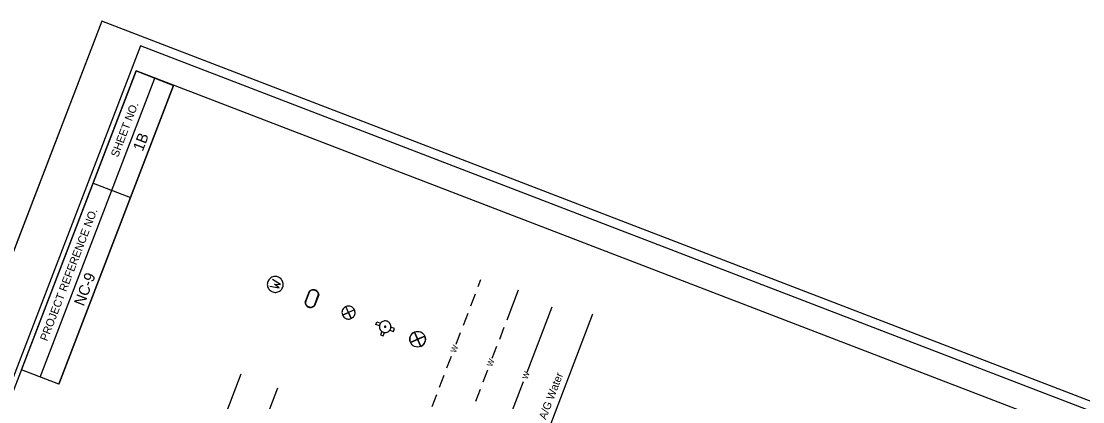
# Model space of a CAD drawing. Extents: x 1015221 to 1064345, y 619216 to 647967.
# Drawn here: x 1047324 to 1051569, y 635845 to 637366 of the extents above; entities that cross this region are included whole.
import ezdxf

# ---------------------------------------------------------------- set-up
doc = ezdxf.new("R2010")
doc.units = 0
for name, color, linetype in [('Default', 7, 'Continuous'), ('Sheet Cutting Line CELL', 7, 'Continuous'), ('Sheet Data Field CELL', 7, 'Continuous'), ('Sheet Plot Border Inside CELL', 7, 'Continuous'), ('Sheet Plot Border Outside CELL', 7, 'Continuous'), ('Sheet Symbology CELL', 7, 'Continuous')]:
    doc.layers.add(name, color=color, linetype=linetype)

msp = doc.modelspace()

# ---------------------------------------------------------------- linework, layer by layer
at = {"layer": 'Default'}
for p, q in [((1049151.2, 636304.8), (1049162.2, 636333.7)), ((1048458.7, 636242.1), (1048476, 636287.1)), ((1048460.2, 636241.5), (1048477.4, 636286.5)), ((1048511.7, 636273), (1048494.6, 636228.3)), ((1048513.2, 636272.5), (1048496, 636227.8)), ((1049121.6, 636227.9), (1049139.9, 636275.5)), ((1049266.5, 636172.3), (1049312.4, 636291.7)), ((1049346.7, 635962.7), (1049447.2, 636224.2)), ((1049092.1, 636151), (1049110.4, 636198.6)), ((1049373.4, 635580.1), (1049609.8, 636195.4)), ((1049237, 636095.3), (1049255.3, 636143)), ((1049062.5, 636074.1), (1049080.8, 636121.7)), ((1049207.4, 636018.4), (1049225.7, 636066.1)), ((1049026.2, 635979.6), (1049044.5, 636027.2)), ((1048201.7, 635954.5), (1047744.7, 634765.2)), ((1049171.1, 635924), (1049189.4, 635971.6)), ((1048996.7, 635902.7), (1049015, 635950.3)), ((1049222.1, 635638.2), (1049332.7, 635926.1)), ((1048348.2, 635898.3), (1047847.2, 634594.3)), ((1048967.1, 635825.8), (1048985.4, 635873.4)), ((1049141.6, 635847.1), (1049159.9, 635894.7))]:
    msp.add_line(p, q, dxfattribs=at)
for points in [[(1048309.9, 636324.9), (1048308.7, 636321), (1048308, 636317.2), (1048307.8, 636313.2), (1048308.2, 636309.2), (1048308.9, 636305.4), (1048310.2, 636301.6), (1048312, 636297.9), (1048314.1, 636294.7), (1048316.7, 636291.5), (1048319.8, 636288.9), (1048323, 636286.6), (1048326.4, 636284.7), (1048330.2, 636283.3), (1048333.9, 636282.4), (1048338.1, 636281.9), (1048341.9, 636281.8), (1048346, 636282.4), (1048349.6, 636283.4), (1048353.5, 636285), (1048357, 636286.9), (1048360.1, 636289.3), (1048363, 636292), (1048365.6, 636295.1), (1048367.7, 636298.6), (1048369.3, 636302.1), (1048370.6, 636306), (1048371.2, 636309.8), (1048371.4, 636313.9), (1048371, 636317.8), (1048370.3, 636321.6), (1048369, 636325.4), (1048367.2, 636329.1), (1048365.1, 636332.4), (1048362.6, 636335.5), (1048359.4, 636338.1), (1048356.2, 636340.4), (1048352.8, 636342.3), (1048349, 636343.7), (1048345.3, 636344.6), (1048341.1, 636345.1), (1048337.3, 636345.2), (1048333.3, 636344.6), (1048329.6, 636343.6), (1048325.7, 636342), (1048322.3, 636340.1), (1048319.2, 636337.7), (1048316.2, 636335.1), (1048313.7, 636331.9), (1048311.5, 636328.4), (1048309.9, 636324.9)], [(1048318.1, 636306.5), (1048355.2, 636299.3), (1048336, 636314.9), (1048360.8, 636313.8), (1048328.4, 636333.4)], [(1048475.9, 636286.8), (1048478.5, 636289.2), (1048481.5, 636291), (1048485.1, 636292.4), (1048488.4, 636293.1), (1048492.2, 636293.4), (1048495.8, 636293), (1048499.1, 636292.1), (1048502.6, 636290.4), (1048505.4, 636288.3), (1048507.8, 636285.7), (1048510.1, 636282.8), (1048511.5, 636279.5), (1048512.6, 636276.1), (1048513.2, 636272.5)], [(1048476.8, 636285.8), (1048479.5, 636288.4), (1048482.9, 636290.2), (1048486, 636291.3), (1048489.6, 636292), (1048493.3, 636291.9), (1048497.1, 636291.1), (1048500.3, 636289.9), (1048503.6, 636288), (1048506.1, 636285.7), (1048508.4, 636282.7), (1048510.1, 636279.4), (1048511.2, 636275.9), (1048511.8, 636272.3)], [(1048458.7, 636242.1), (1048459, 636238.6), (1048460.1, 636235.2), (1048461.8, 636231.8), (1048463.8, 636229), (1048466.4, 636226.3), (1048469.3, 636224.2), (1048472.5, 636222.6), (1048476.1, 636221.6), (1048479.7, 636221.2), (1048483.2, 636221.6), (1048486.8, 636222.2), (1048490.1, 636223.6), (1048493.1, 636225.5), (1048496, 636227.8)], [(1048460.1, 636242.3), (1048460.7, 636238.6), (1048461.8, 636235.2), (1048463.5, 636231.8), (1048465.5, 636229), (1048468.3, 636226.6), (1048471.6, 636224.7), (1048474.8, 636223.4), (1048478.3, 636222.8), (1048481.9, 636222.7), (1048485.6, 636223.3), (1048489.1, 636224.7), (1048492.2, 636226.5), (1048494.8, 636228.9)], [(1048641.9, 636225.3), (1048638.3, 636226.4), (1048634.2, 636227), (1048630.5, 636226.9), (1048626.5, 636226.2), (1048622.9, 636225.1), (1048619.5, 636223.4), (1048616.2, 636221.2), (1048613.3, 636218.6), (1048610.9, 636215.5), (1048609, 636212.2), (1048607.5, 636208.4), (1048606.7, 636204.7), (1048606.4, 636200.8), (1048606.8, 636196.9), (1048607.8, 636193.1), (1048609.2, 636189.5), (1048611.1, 636186.2), (1048613.6, 636183.1), (1048616.3, 636180.5), (1048619.8, 636178.2), (1048623.2, 636176.6), (1048626.8, 636175.5), (1048630.9, 636174.9), (1048634.7, 636175), (1048638.7, 636175.7), (1048642.2, 636176.8), (1048645.7, 636178.5), (1048649, 636180.7), (1048651.9, 636183.3), (1048654.3, 636186.4), (1048656.2, 636189.7), (1048657.6, 636193.5), (1048658.5, 636197.2), (1048658.7, 636201.1), (1048658.3, 636205), (1048657.3, 636208.8), (1048655.9, 636212.4), (1048654, 636215.7), (1048651.5, 636218.8), (1048648.8, 636221.4), (1048645.3, 636223.7), (1048641.9, 636225.3)], [(1048656.5, 636211.6), (1048608.6, 636190.3), (1048632.6, 636201), (1048643.2, 636177), (1048621.9, 636224.9)], [(1048757.3, 636152.7), (1048756.3, 636149.2), (1048755.8, 636145.5), (1048755.9, 636141.6), (1048756.8, 636138), (1048758.1, 636134.7), (1048760.1, 636131.3), (1048762.5, 636128.4), (1048765.4, 636126), (1048768.5, 636123.9), (1048771.9, 636122.6), (1048775.5, 636121.9), (1048779.2, 636121.4), (1048782.9, 636121.9), (1048786.5, 636122.8), (1048790, 636124.3), (1048793.3, 636126.3), (1048795.9, 636128.8), (1048798.3, 636131.8), (1048800.2, 636135), (1048801.5, 636138.3), (1048802.2, 636141.9), (1048802.1, 636145.8), (1048801.9, 636149.5), (1048800.7, 636153.1), (1048799, 636156.4), (1048797, 636159.4), (1048794.2, 636162.1), (1048791.2, 636164.5), (1048787.9, 636166.1), (1048784.5, 636167.1), (1048780.9, 636167.8), (1048777, 636167.7), (1048773.2, 636167.2), (1048769.8, 636166), (1048766.5, 636164), (1048763.4, 636162), (1048761, 636159), (1048758.9, 636156), (1048757.3, 636152.7)], [(1048755.9, 636147.4), (1048741.9, 636152.8), (1048746.2, 636164.1), (1048760.5, 636158.6)], [(1048765.4, 636126), (1048760, 636112), (1048771.3, 636107.7), (1048776.7, 636121.7)], [(1048776.5, 636145.6), (1048776.4, 636144.4), (1048776.9, 636143.2), (1048777.8, 636142.2), (1048779, 636142.1), (1048780.4, 636142.2), (1048781.4, 636143.1), (1048781.8, 636144.3), (1048781.7, 636145.6), (1048780.8, 636146.6), (1048779.8, 636147.3), (1048778.4, 636147.2), (1048777.2, 636146.7), (1048776.5, 636145.6)], [(1048798.1, 636131.2), (1048812.1, 636125.8), (1048816.5, 636137.1), (1048802.1, 636142.6)], [(1048896.1, 636123.2), (1048921.6, 636065.9), (1048908.8, 636094.5), (1048880.2, 636081.8), (1048937.5, 636107.3)], [(1048880.2, 636081.8), (1048908.8, 636094.5), (1048896.1, 636123.2)], [(1048937.5, 636107.3), (1048908.8, 636094.5), (1048921.6, 636065.9)]]:
    msp.add_lwpolyline(points, dxfattribs=at)
msp.add_circle((1048908.8, 636094.5), 31.4, dxfattribs=at)
for start, end in [(113.983, 203.983), (293.983, 23.983)]:
    msp.add_arc((1048908.8, 636094.5), 31.4, start, end, dxfattribs=at)
at = {"layer": 'Sheet Cutting Line CELL'}
msp.add_line((1047645.6, 637365.6), (1042813.9, 624789.8), dxfattribs=at)
at = {"layer": 'Sheet Plot Border Inside CELL'}
msp.add_lwpolyline([(1050898.2, 621795.3), (1055679.6, 634240.3), (1047800.3, 637267.6), (1043018.9, 624822.5)], close=True, dxfattribs=at)
at = {"layer": 'Sheet Plot Border Outside CELL'}
msp.add_lwpolyline([(1051028.5, 621633.8), (1055860.2, 634209.5), (1047645.6, 637365.6), (1042813.9, 624789.8)], close=True, dxfattribs=at)
at = {"layer": 'Sheet Symbology CELL'}
for p, q in [((1047399.3, 635943), (1047858.5, 637138.1)), ((1047474, 635914.3), (1047933.1, 637109.4)), ((1047611.6, 636718.8), (1047761, 636661.4))]:
    msp.add_line(p, q, dxfattribs=at)
for points in [[(1047783.5, 637166.9), (1043479.8, 625965.2), (1051313.4, 622955.5), (1055617.1, 634157.2)], [(1047324.3, 635971.8), (1047783.5, 637166.9), (1047933.1, 637109.4), (1047474, 635914.3)]]:
    msp.add_lwpolyline(points, close=True, dxfattribs=at)

# ---------------------------------------------------------------- texts
at = {"layer": 'Default'}
for s, height, p in [('W', 23.5, (1049061.4, 636038.4)), ('W', 23.5, (1049206.3, 635982.7)), ('W', 23.5, (1049347.6, 635932.1)), ('A/G Water', 31.38, (1049421.6, 635771.1))]:
    msp.add_text(s, height=height, rotation=68.983, dxfattribs=at).set_placement(p)
at = {"layer": 'Sheet Data Field CELL'}
for s, p in [('1B ', (1047809.3, 636843)), ('NC-9', (1047573.5, 636224.1))]:
    msp.add_text(s, height=43.2, rotation=68.983, dxfattribs=at).set_placement(p)
at = {"layer": 'Sheet Symbology CELL'}
for s, p in [('SHEET NO.', (1047710.5, 636819.9)), ('PROJECT REFERENCE NO.', (1047427.3, 636084.5))]:
    msp.add_text(s, height=32, rotation=68.983, dxfattribs=at).set_placement(p)

doc.saveas('drawing.dxf')
